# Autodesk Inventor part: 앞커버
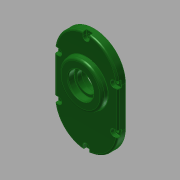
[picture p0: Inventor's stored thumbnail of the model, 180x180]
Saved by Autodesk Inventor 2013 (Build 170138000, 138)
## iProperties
Created: 2016-12
Part Number: 앞커버
Material: 일반
Document SubType Name: Modeling
Designer: mduedu
Density: 1 g/cm^3
Author: mduedu
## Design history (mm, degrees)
sketch "스케치1"
  geometry: L1 (40, -25)-(40, 25); L2 (-40, 25)-(-40, -25); L3 (-40, -25)-(40, 25); L4 (40, -25)-(-40, 25); A1 r 40 centre (0, 25) between (40, 25) and (-40, 25); A2 r 40 centre (0, -25) between (-40, -25) and (40, -25); 1 further point
  constraints: 8 end point, 4 point on circle, 4 tangent, 2 centre point, 2 midpoint, 1 parallel, 1 vertical
  dimensions: "d0" = 130 dimension on A2 A1; "d2" = 80 distance between parallel lines of L1 L2
extrude "돌출1" new body sketch "스케치1" distance "d3" = 10; taper "d4" = 0 deg
sketch "스케치2"
  geometry: C1 r 21 at (0, 11); 1 further point
  constraints: 1 centre point, 1 vertical alignment
  dimensions: "d5" = 42 diameter of C1; "d7" = 11 distance of C1.centre point (0, 0)
extrude "돌출2" join sketch "스케치2" distance "d8" = 7; taper "d9" = 0 deg
sketch "스케치3"
  geometry: C1 r 15 at (0, -33.1); C2 r 21 at (0, 11) reference; 1 further point
  constraints: 1 centre point, 1 vertical alignment
  dimensions: "d10" = 30 diameter of C1; "d71" = 44.1 distance of C1.centre C2.centre
extrude "돌출3" join sketch "스케치3" distance "d12" = 7; taper "d13" = 0 deg
sketch "스케치4"
  geometry: C1 r 28 at (0, 11); A1 r 21 centre (0, 11) between (8.978, -7.984) and (-8.978, -7.984) reference; 1 further point
  constraints: 1 centre point, 1 coincident
  dimensions: "d14" = 56 diameter of C1
extrude "돌출4" join sketch "스케치4" distance "d15" = 7; taper "d16" = -5 deg
hole "구멍1" diameter "d19" = 35; stored, may be unused: countersink angle "d23" = 90 deg, drill point angle "d25" = 0 deg; dims "d17" = 10, "d18" = 10, "d20" = 6, "d21" = 4, "d22" = 2, "d24" = 10
hole "구멍2" diameter "d28" = 22; stored, may be unused: countersink angle "d32" = 90 deg, drill point angle "d34" = 0 deg; dims "d26" = 10, "d27" = 10, "d29" = 6, "d30" = 4, "d31" = 2, "d33" = 7
hole "구멍3" diameter "d37" = 19; stored, may be unused: countersink angle "d41" = 90 deg, drill point angle "d43" = 0 deg; dims "d35" = 10, "d36" = 10, "d38" = 6, "d39" = 4, "d40" = 2, "d42" = 1
hole "구멍4" diameter "d46" = 32; stored, may be unused: countersink angle "d50" = 90 deg, drill point angle "d52" = 0 deg; dims "d44" = 10, "d45" = 10, "d47" = 6, "d48" = 4, "d49" = 2, "d51" = 8
hole "구멍5" diameter "d55" = 25; stored, may be unused: countersink angle "d59" = 90 deg, drill point angle "d61" = 0 deg; dims "d53" = 10, "d54" = 10, "d56" = 6, "d57" = 4, "d58" = 2, "d60" = 8
fillet "모깎기1" dims "d62" = 0.3
fillet "모깎기2" dims "d63" = 2
chamfer "모따기1" distance "d64" = 1; stored, may be unused: second distance "d65" = 2, angle "d66" = 45 deg
fillet "모깎기4" dims "d68" = 2
fillet "모깎기5" dims "d69" = 0.3
fillet "모깎기6" dims "d70" = 2
sketch "스케치5"
  geometry: L1 (-40, 25)-(-40, -25) reference; L2 (40, -25)-(40, 25) reference; L3 (35, 25)-(35, -25); L4 (-35, -25)-(-35, 25); A1 r 40 centre (0, 25) between (40, 25) and (-40, 25) reference; A2 r 40 centre (0, -25) between (-40, -25) and (40, -25) reference; A3 r 35 centre (0, 25) between (35, 25) and (-35, 25); A4 r 35 centre (0, -25) between (-35, -25) and (35, -25); 2 further points
  constraints: 5 point on circle, 4 end point, 2 centre point, 1 vertical alignment, 3 other
  dimensions: "d72" = 5 distance between parallel lines of L2 L3
sketch "스케치7"
  geometry: 1 further point
hole "구멍7" sketch "스케치7" at (0, 60) diameter "d80" = 4.5; stored, may be unused: countersink angle "d84" = 90 deg, drill point angle "d86" = 0 deg; dims "d81" = 6, "d82" = 8, "d83" = 4.6, "d85" = 8
sketch "스케치9"
  geometry: L1 (-4, 0)-(4, 0); L2 (4, 0)-(4, 5); L3 (4, 5)-(-4, 5); L4 (-4, 5)-(-4, 0); C1 r 2.25 at (0, 0) reference; A1 r 40 centre (0, -35) between (40, -35) and (-40, -35) reference; 2 further points
  constraints: 8 end point, 2 parallel, 2 vertical, 1 horizontal, 1 horizontal alignment, 1 perpendicular, 1 tangent, 1 other
extrude "돌출6" cut sketch "스케치9" stored distance "d96" = 3; taper "d97" = 0 deg
fillet "모깎기7" dims "d98" = 0.3
fillet "모깎기8" dims "d99" = 0.3
fillet "모깎기9" dims "d100" = 3
node "솔리드1"
pattern_linear "직사각형 패턴1"
node "투영된 루프1"
